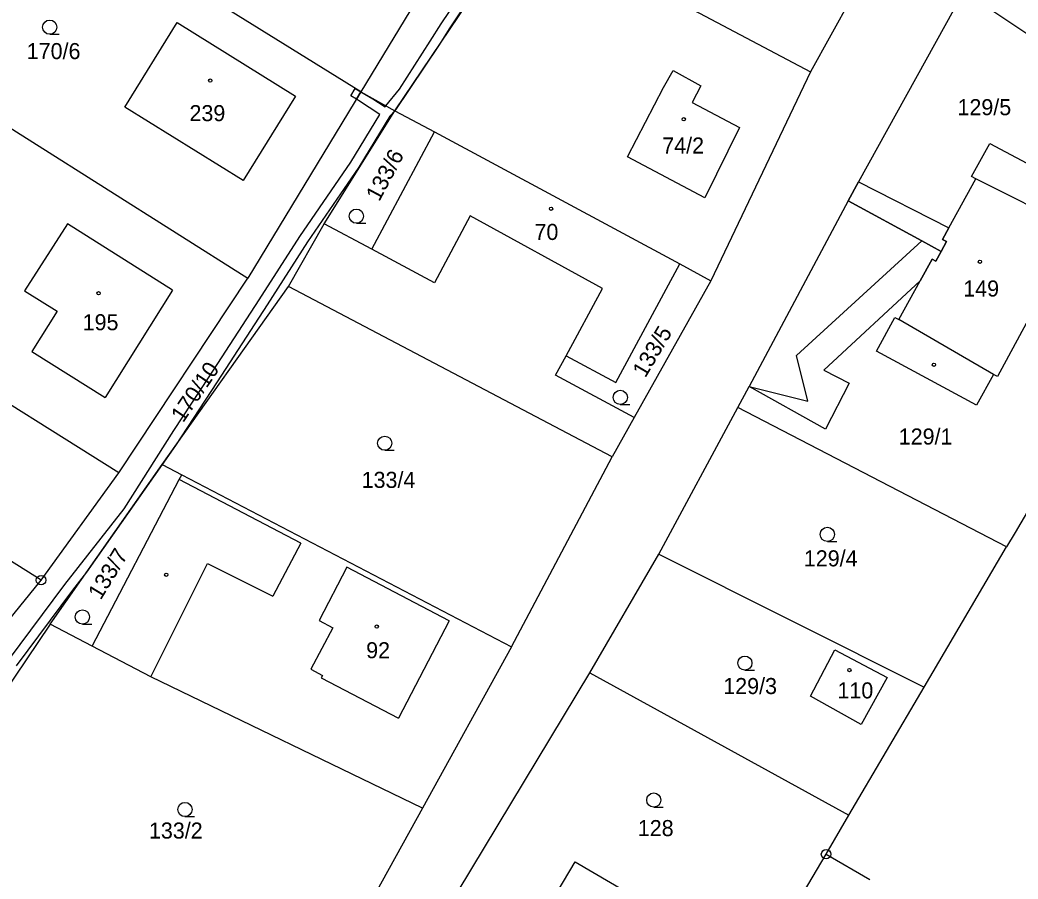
# Model space of a CAD drawing. Extents: x -747333 to -745433, y -1133152 to -1130600.
# Drawn here: x -746442.1 to -746336.5, y -1131952.5 to -1131861.6 of the extents above; entities that cross this region are included whole.
import ezdxf

# ---------------------------------------------------------------- set-up
doc = ezdxf.new("R2010")
doc.units = 0
for name, color, linetype in [('Vrstva 1', 7, 'Continuous'), ('Vrstva 18', 7, 'Continuous'), ('Vrstva 19', 7, 'Continuous'), ('Vrstva 24', 7, 'Continuous'), ('Vrstva 25', 7, 'Continuous'), ('Vrstva 3', 7, 'Continuous'), ('Vrstva 30', 7, 'Continuous'), ('Vrstva 37', 7, 'Continuous'), ('Vrstva 4', 7, 'Continuous')]:
    doc.layers.add(name, color=color, linetype=linetype)

msp = doc.modelspace()

# ---------------------------------------------------------------- linework, layer by layer
at = {"layer": 'Vrstva 1'}
for points in [[(-746347.69, -1131847.59), (-746358.44, -1131867.04)], [(-746394.96, -1131850.9), (-746406.07, -1131869.18)], [(-746402.47, -1131871.17), (-746388.82, -1131850.94)], [(-746388.82, -1131850.94), (-746358.44, -1131867.04)], [(-746406.07, -1131869.18), (-746427.32, -1131855.97)], [(-746342.22, -1131858.51), (-746353.37, -1131878.68)], [(-746342.22, -1131858.51), (-746319.24, -1131873.86)], [(-746431.03, -1131870.79), (-746425.5, -1131861.83)], [(-746425.5, -1131861.83), (-746412.97, -1131869.62)], [(-746455.99, -1131864.91), (-746418.01, -1131888.89)], [(-746358.44, -1131867.04), (-746369.01, -1131889.16)], [(-746412.97, -1131869.62), (-746418.52, -1131878.56)], [(-746406.07, -1131869.18), (-746418.01, -1131888.89)], [(-746406.07, -1131869.18), (-746402.47, -1131871.17)], [(-746418.52, -1131878.56), (-746431.03, -1131870.79)], [(-746409.94, -1131883.15), (-746402.47, -1131871.17)], [(-746402.47, -1131871.17), (-746398.27, -1131873.41)], [(-746404.9, -1131885.84), (-746398.27, -1131873.41)], [(-746398.27, -1131873.41), (-746372.28, -1131887.39)], [(-746341.38, -1131878.14), (-746339.47, -1131874.63)], [(-746339.47, -1131874.63), (-746328.89, -1131880.25)], [(-746343.79, -1131883.58), (-746340.94, -1131878.38)], [(-746340.94, -1131878.38), (-746341.38, -1131878.14)], [(-746353.37, -1131878.68), (-746354.46, -1131880.72)], [(-746354.46, -1131880.72), (-746364.94, -1131900.36)], [(-746354.46, -1131880.72), (-746346.67, -1131884.94)], [(-746437.12, -1131883.14), (-746441.65, -1131890.22)], [(-746426.01, -1131890.18), (-746437.12, -1131883.14)], [(-746413.73, -1131889.78), (-746409.94, -1131883.15)], [(-746404.9, -1131885.84), (-746409.94, -1131883.15)], [(-746344.46, -1131884.81), (-746343.79, -1131883.58)], [(-746431.68, -1131909.51), (-746469.48, -1131885.78)], [(-746346.67, -1131884.94), (-746344.6, -1131886.06)], [(-746344.6, -1131886.06), (-746344.04, -1131885.02)], [(-746344.04, -1131885.02), (-746344.46, -1131884.81)], [(-746346.84, -1131889.17), (-746345.57, -1131886.87)], [(-746345.57, -1131886.87), (-746345.17, -1131887.1)], [(-746345.17, -1131887.1), (-746344.6, -1131886.06)], [(-746379.07, -1131899.95), (-746372.28, -1131887.39)], [(-746372.28, -1131887.39), (-746369.01, -1131889.16)], [(-746431.68, -1131909.51), (-746418.01, -1131888.89)], [(-746427.09, -1131908.61), (-746413.73, -1131889.78)], [(-746379.44, -1131907.81), (-746413.73, -1131889.78)], [(-746369.01, -1131889.16), (-746377.12, -1131903.66)], [(-746349.1, -1131893.27), (-746346.84, -1131889.17)], [(-746441.65, -1131890.22), (-746438.2, -1131892.39)], [(-746426.01, -1131890.18), (-746433.13, -1131901.53)], [(-746438.2, -1131892.39), (-746440.88, -1131896.67)], [(-746351.45, -1131896.64), (-746349.5, -1131893.05)], [(-746349.5, -1131893.05), (-746349.1, -1131893.27)], [(-746335.16, -1131892.84), (-746338.66, -1131899.32)], [(-746440.88, -1131896.67), (-746433.13, -1131901.53)], [(-746385.43, -1131899.17), (-746384.32, -1131897.11)], [(-746384.32, -1131897.11), (-746379.07, -1131899.95)], [(-746340.87, -1131902.35), (-746351.45, -1131896.64)], [(-746377.12, -1131903.66), (-746385.43, -1131899.17)], [(-746339.07, -1131899.09), (-746340.87, -1131902.35)], [(-746338.66, -1131899.32), (-746339.07, -1131899.09)], [(-746366.14, -1131902.59), (-746364.94, -1131900.36)], [(-746374.51, -1131918.11), (-746366.14, -1131902.59)], [(-746337.68, -1131917.35), (-746366.14, -1131902.59)], [(-746377.12, -1131903.66), (-746379.44, -1131907.81)], [(-746439.92, -1131920.87), (-746465.42, -1131904.8)], [(-746331.51, -1131906.85), (-746336.79, -1131915.84)], [(-746390.09, -1131927.94), (-746379.44, -1131907.81)], [(-746438.95, -1131925.52), (-746427.09, -1131908.61)], [(-746427.09, -1131908.61), (-746425.01, -1131909.7)], [(-746439.92, -1131920.87), (-746431.68, -1131909.51)], [(-746425.29, -1131910.22), (-746425.01, -1131909.7)], [(-746425.01, -1131909.7), (-746390.09, -1131927.94)], [(-746434.5, -1131927.85), (-746425.29, -1131910.22)], [(-746336.79, -1131915.84), (-746337.68, -1131917.35)], [(-746346.4, -1131932.2), (-746337.68, -1131917.35)], [(-746381.8, -1131930.69), (-746374.51, -1131918.11)], [(-746374.51, -1131918.11), (-746346.4, -1131932.2)], [(-746454.36, -1131938.7), (-746439.92, -1131920.87)], [(-746438.95, -1131925.52), (-746453.89, -1131947.67)], [(-746434.5, -1131927.85), (-746438.95, -1131925.52)], [(-746428.29, -1131931.1), (-746434.5, -1131927.85)], [(-746390.09, -1131927.94), (-746399.53, -1131945)], [(-746358.46, -1131933.16), (-746355.85, -1131928.24)], [(-746355.85, -1131928.24), (-746350.32, -1131931.16)], [(-746399.53, -1131945), (-746428.29, -1131931.1)], [(-746395.75, -1131953.81), (-746381.8, -1131930.69)], [(-746381.8, -1131930.69), (-746354.37, -1131945.76)], [(-746350.32, -1131931.16), (-746353.09, -1131936.15)], [(-746354.37, -1131945.76), (-746346.4, -1131932.2)], [(-746353.09, -1131936.15), (-746358.46, -1131933.16)], [(-746399.53, -1131945), (-746408.25, -1131960.77)], [(-746356.8, -1131949.89), (-746354.37, -1131945.76)], [(-746364, -1131962.05), (-746356.8, -1131949.89)], [(-746356.8, -1131949.89), (-746352.16, -1131952.55)], [(-746387.94, -1131958.43), (-746383.37, -1131950.7)], [(-746383.37, -1131950.7), (-746369.24, -1131958.95)]]:
    msp.add_lwpolyline(points, dxfattribs=at)
at = {"layer": 'Vrstva 24'}
for p, q in [((-746439.97, -1131920.87), (-746439.87, -1131920.87)), ((-746356.85, -1131949.89), (-746356.75, -1131949.89))]:
    msp.add_line(p, q, dxfattribs=at)
for centre in [(-746439.92, -1131920.87), (-746356.8, -1131949.89)]:
    msp.add_circle(centre, 0.499289, dxfattribs=at)
at = {"layer": 'Vrstva 25'}
for p, q in [((-746439, -1131863.07), (-746438, -1131863.07)), ((-746406.53, -1131883.08), (-746405.53, -1131883.08)), ((-746378.58, -1131902.27), (-746377.58, -1131902.27)), ((-746403.53, -1131907.12), (-746402.53, -1131907.12)), ((-746356.66, -1131916.77), (-746355.66, -1131916.77)), ((-746435.54, -1131925.52), (-746434.54, -1131925.52)), ((-746365.39, -1131930.4), (-746364.39, -1131930.4)), ((-746375.04, -1131944.9), (-746374.04, -1131944.9)), ((-746424.68, -1131945.9), (-746423.68, -1131945.9))]:
    msp.add_line(p, q, dxfattribs=at)
for centre, radius in [((-746439, -1131862.32), 0.75), ((-746422, -1131867.98), 0.174503), ((-746371.86, -1131872.07), 0.174503), ((-746406.53, -1131882.33), 0.75), ((-746385.91, -1131881.55), 0.174503), ((-746340.5, -1131887.16), 0.174503), ((-746433.82, -1131890.49), 0.174503), ((-746345.37, -1131898.07), 0.174503), ((-746378.58, -1131901.52), 0.75), ((-746403.53, -1131906.37), 0.75), ((-746356.66, -1131916.02), 0.75), ((-746426.66, -1131920.3), 0.174503), ((-746435.54, -1131924.77), 0.75), ((-746404.37, -1131925.78), 0.174503), ((-746365.39, -1131929.65), 0.75), ((-746354.32, -1131930.39), 0.174503), ((-746375.04, -1131944.15), 0.75), ((-746424.68, -1131945.15), 0.75)]:
    msp.add_circle(centre, radius, dxfattribs=at)
at = {"layer": 'Vrstva 3'}
for points in [[(-746431.03, -1131870.79), (-746425.5, -1131861.83)], [(-746425.5, -1131861.83), (-746412.97, -1131869.62)], [(-746374.01, -1131868.72), (-746373, -1131866.91)], [(-746373, -1131866.91), (-746370.05, -1131868.52)], [(-746377.83, -1131876.03), (-746374.01, -1131868.72)], [(-746370.05, -1131868.52), (-746370.98, -1131870.31)], [(-746412.97, -1131869.62), (-746418.52, -1131878.56)], [(-746418.52, -1131878.56), (-746431.03, -1131870.79)], [(-746370.98, -1131870.31), (-746365.95, -1131872.95)], [(-746365.95, -1131872.95), (-746369.63, -1131880.4)], [(-746404.9, -1131885.84), (-746398.27, -1131873.41)], [(-746398.27, -1131873.41), (-746372.28, -1131887.39)], [(-746369.63, -1131880.4), (-746377.83, -1131876.03)], [(-746343.79, -1131883.58), (-746340.94, -1131878.38)], [(-746330.66, -1131883.52), (-746340.94, -1131878.38)], [(-746394.49, -1131882.3), (-746398.26, -1131889.38)], [(-746380.47, -1131889.98), (-746394.49, -1131882.3)], [(-746437.12, -1131883.14), (-746441.65, -1131890.22)], [(-746426.01, -1131890.18), (-746437.12, -1131883.14)], [(-746344.46, -1131884.81), (-746343.79, -1131883.58)], [(-746398.26, -1131889.38), (-746404.9, -1131885.84)], [(-746344.6, -1131886.06), (-746344.04, -1131885.02)], [(-746344.04, -1131885.02), (-746344.46, -1131884.81)], [(-746346.84, -1131889.17), (-746345.57, -1131886.87)], [(-746345.57, -1131886.87), (-746345.17, -1131887.1)], [(-746345.17, -1131887.1), (-746344.6, -1131886.06)], [(-746379.07, -1131899.95), (-746372.28, -1131887.39)], [(-746384.32, -1131897.11), (-746380.47, -1131889.98)], [(-746349.1, -1131893.27), (-746346.84, -1131889.17)], [(-746441.65, -1131890.22), (-746438.2, -1131892.39)], [(-746426.01, -1131890.18), (-746433.13, -1131901.53)], [(-746438.2, -1131892.39), (-746440.88, -1131896.67)], [(-746335.16, -1131892.84), (-746338.66, -1131899.32)], [(-746339.07, -1131899.09), (-746349.1, -1131893.27)], [(-746440.88, -1131896.67), (-746433.13, -1131901.53)], [(-746384.32, -1131897.11), (-746379.07, -1131899.95)], [(-746338.66, -1131899.32), (-746339.07, -1131899.09)], [(-746407.53, -1131919.5), (-746410.48, -1131925.14)], [(-746396.69, -1131925.16), (-746407.53, -1131919.5)], [(-746409.03, -1131925.9), (-746411.35, -1131930.29)], [(-746410.48, -1131925.14), (-746409.03, -1131925.9)], [(-746396.69, -1131925.16), (-746402.08, -1131935.48)], [(-746358.46, -1131933.16), (-746355.85, -1131928.24)], [(-746355.85, -1131928.24), (-746350.32, -1131931.16)], [(-746411.35, -1131930.29), (-746410.1, -1131930.95)], [(-746410.1, -1131930.95), (-746410.24, -1131931.22)], [(-746410.24, -1131931.22), (-746402.08, -1131935.48)], [(-746350.32, -1131931.16), (-746353.09, -1131936.15)], [(-746353.09, -1131936.15), (-746358.46, -1131933.16)]]:
    msp.add_lwpolyline(points, dxfattribs=at)
at = {"layer": 'Vrstva 30'}
for points in [[(-746397.55, -1131861.96), (-746395.73, -1131859.2)], [(-746394.59, -1131859.3), (-746396.71, -1131862.5)], [(-746398.7, -1131863.81), (-746397.55, -1131861.96)], [(-746396.71, -1131862.5), (-746397.75, -1131864.18)], [(-746397.75, -1131864.18), (-746402.47, -1131871.17)], [(-746401.96, -1131868.88), (-746398.7, -1131863.81)], [(-746407.12, -1131869.6), (-746406.66, -1131868.81)], [(-746406.66, -1131868.81), (-746406.07, -1131869.18)], [(-746403.4, -1131870.66), (-746401.96, -1131868.88)], [(-746406.53, -1131869.94), (-746407.12, -1131869.6)], [(-746406.53, -1131869.94), (-746406.07, -1131869.18)], [(-746406.07, -1131869.18), (-746406.53, -1131869.94)], [(-746406.29, -1131870.08), (-746406.53, -1131869.94)], [(-746406.07, -1131869.18), (-746404.78, -1131869.89)], [(-746404.78, -1131869.89), (-746403.49, -1131870.77)], [(-746404.05, -1131871.58), (-746406.29, -1131870.08)], [(-746403.49, -1131870.77), (-746403.4, -1131870.66)], [(-746407.12, -1131876.61), (-746404.05, -1131871.58)], [(-746402.97, -1131871.73), (-746406.28, -1131877.15)], [(-746402.47, -1131871.17), (-746402.97, -1131871.73)], [(-746412.52, -1131884.47), (-746407.12, -1131876.61)], [(-746406.28, -1131877.15), (-746411.69, -1131885.03)], [(-746353.37, -1131878.68), (-746343.79, -1131883.58), (-746344.46, -1131884.81), (-746344.04, -1131885.02), (-746344.6, -1131886.06), (-746346.67, -1131884.94), (-746354.46, -1131880.72), (-746353.37, -1131878.68)], [(-746416.82, -1131891.18), (-746412.52, -1131884.47)], [(-746411.69, -1131885.03), (-746415.98, -1131891.72)], [(-746344.6, -1131886.06), (-746345.17, -1131887.1), (-746345.57, -1131886.87), (-746346.84, -1131889.17), (-746357.02, -1131898.63), (-746354.35, -1131900.01), (-746356.86, -1131904.88), (-746364.94, -1131900.36), (-746358.72, -1131901.91), (-746359.94, -1131897.08), (-746346.67, -1131884.94), (-746344.6, -1131886.06)], [(-746422.12, -1131899.33), (-746416.82, -1131891.18)], [(-746415.98, -1131891.72), (-746421.28, -1131899.88)], [(-746425.85, -1131905.03), (-746422.12, -1131899.33)], [(-746421.28, -1131899.88), (-746425.67, -1131906.6)], [(-746431.13, -1131913.33), (-746425.85, -1131905.03)], [(-746425.67, -1131906.6), (-746427.09, -1131908.61)], [(-746427.09, -1131908.61), (-746435.09, -1131920.01)], [(-746437.38, -1131921.32), (-746431.13, -1131913.33)], [(-746435.09, -1131920.01), (-746436.58, -1131921.92)], [(-746443.35, -1131929.34), (-746437.38, -1131921.32)], [(-746436.58, -1131921.92), (-746442.55, -1131929.94)]]:
    msp.add_lwpolyline(points, dxfattribs=at)
at = {"layer": 'Vrstva 37'}
for centre in [(-746422, -1131867.98), (-746371.86, -1131872.07), (-746385.91, -1131881.55), (-746340.5, -1131887.16), (-746433.82, -1131890.49), (-746404.37, -1131925.78), (-746354.32, -1131930.39)]:
    msp.add_circle(centre, 0.174503, dxfattribs=at)
at = {"layer": 'Vrstva 4'}
for points in [[(-746374.01, -1131868.72), (-746373, -1131866.91)], [(-746373, -1131866.91), (-746370.05, -1131868.52)], [(-746377.83, -1131876.03), (-746374.01, -1131868.72)], [(-746370.05, -1131868.52), (-746370.98, -1131870.31)], [(-746370.98, -1131870.31), (-746365.95, -1131872.95)], [(-746365.95, -1131872.95), (-746369.63, -1131880.4)], [(-746369.63, -1131880.4), (-746377.83, -1131876.03)], [(-746330.66, -1131883.52), (-746340.94, -1131878.38)], [(-746394.49, -1131882.3), (-746398.26, -1131889.38)], [(-746380.47, -1131889.98), (-746394.49, -1131882.3)], [(-746398.26, -1131889.38), (-746404.9, -1131885.84)], [(-746384.32, -1131897.11), (-746380.47, -1131889.98)], [(-746339.07, -1131899.09), (-746349.1, -1131893.27)], [(-746412.42, -1131916.94), (-746425.29, -1131910.22)], [(-746412.42, -1131916.94), (-746415.37, -1131922.58)], [(-746428.29, -1131931.1), (-746422.28, -1131919.11)], [(-746422.28, -1131919.11), (-746415.37, -1131922.58)], [(-746407.53, -1131919.5), (-746410.48, -1131925.14)], [(-746396.69, -1131925.16), (-746407.53, -1131919.5)], [(-746409.03, -1131925.9), (-746411.35, -1131930.29)], [(-746410.48, -1131925.14), (-746409.03, -1131925.9)], [(-746396.69, -1131925.16), (-746402.08, -1131935.48)], [(-746411.35, -1131930.29), (-746410.1, -1131930.95)], [(-746410.1, -1131930.95), (-746410.24, -1131931.22)], [(-746410.24, -1131931.22), (-746402.08, -1131935.48)]]:
    msp.add_lwpolyline(points, dxfattribs=at)

# ---------------------------------------------------------------- texts
at = {"layer": 'Vrstva 18'}
for s, p in [('170/6', (-746441.43, -1131865.7)), ('129/5', (-746342.88, -1131871.64)), ('129/1', (-746349.1, -1131906.51)), ('133/4', (-746405.97, -1131911.1)), ('129/4', (-746359.15, -1131919.41)), ('129/3', (-746367.68, -1131932.93)), ('133/2', (-746428.49, -1131948.23)), ('128', (-746376.73, -1131947.97))]:
    msp.add_text(s, height=1.7, dxfattribs=at).set_placement(p)
for s, rotation, p in [('133/6', 61.95528, (-746404.11, -1131880.86)), ('133/5', 59.36139, (-746375.93, -1131899.52)), ('170/10', 55.86723, (-746424.87, -1131904.27)), ('133/7', 58.60611, (-746433.6, -1131923.05))]:
    msp.add_text(s, height=1.7, rotation=rotation, dxfattribs=at).set_placement(p)
at = {"layer": 'Vrstva 19'}
for s, p in [('239', (-746424.2, -1131872.27)), ('74/2', (-746374.14, -1131875.7)), ('70', (-746387.67, -1131884.85)), ('149', (-746342.27, -1131890.84)), ('195', (-746435.51, -1131894.41)), ('92', (-746405.49, -1131929.14)), ('110', (-746355.59, -1131933.39))]:
    msp.add_text(s, height=1.7, dxfattribs=at).set_placement(p)

doc.saveas('drawing.dxf')
